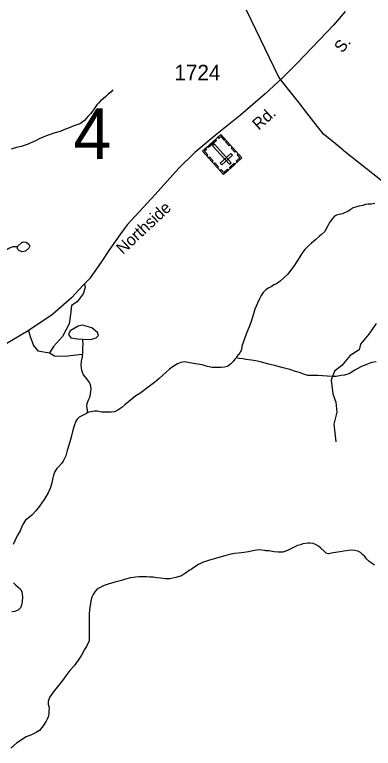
# Model space of a CAD drawing. Extents: x 2056842 to 2160602, y 826753 to 1016856.
# Drawn here: x 2087342 to 2090235, y 854040 to 859964 of the extents above; entities that cross this region are included whole.
import ezdxf

# ---------------------------------------------------------------- set-up
doc = ezdxf.new("R2010")
doc.units = 0
for name, color, linetype in [('Exist Boundary Political City Limit New', 7, 'Continuous'), ('Exist Cultural Cemetery CELL', 7, 'Continuous'), ('Exist Hydrographic Creek Single Shore', 7, 'Continuous'), ('Exist Hydrographic Misc Water Feature', 7, 'Continuous'), ('Exist Road Non-System Type 51', 7, 'Continuous'), ('Exist Road Secondary Structure Standard Bridge Number Label', 7, 'Continuous'), ('Exist Road Secondary Type 51 Attributed', 7, 'Continuous'), ('Exist Road Secondary Type 51 Label', 7, 'Continuous'), ('Exist Road Secondary Type 51 Number Label', 7, 'Continuous'), ('Map Preparation Boundary City Limit Buffer Line', 7, 'Continuous')]:
    doc.layers.add(name, color=color, linetype=linetype)

msp = doc.modelspace()

# ---------------------------------------------------------------- linework, layer by layer
at = {"layer": 'Exist Boundary Political City Limit New'}
msp.add_lwpolyline([(2091735, 858766.5), (2090411.6, 858536.4), (2090000, 858863), (2089992.9, 858868.9), (2089910.4, 858937), (2089833.6, 859000.2), (2089688.6, 859184.9), (2089636.1, 859251.8), (2089509.2, 859414.6), (2089471.8, 859460.8), (2089211, 860000)], dxfattribs=at)
at = {"layer": 'Exist Cultural Cemetery CELL'}
for points in [[(2089175.2, 858807), (2089027.4, 858673.7), (2088856.9, 858862.9), (2089004.8, 858996.2)], [(2088969.8, 858949.2), (2088906.7, 858892.3), (2088899.1, 858900.8), (2088962.1, 858957.6)], [(2088980.2, 858974), (2088987.9, 858965.4), (2089004.3, 858980.2), (2089031.3, 858950.2), (2089039.6, 858957.6), (2089004.8, 858996.2)], [(2089051.6, 858944.2), (2089080.6, 858912.1), (2089072.2, 858904.4), (2089043.2, 858936.6)], [(2088881.5, 858885), (2088889.2, 858876.5), (2088872.8, 858861.8), (2088899.9, 858831.8), (2088891.6, 858824.3), (2088856.9, 858862.9)], [(2089074.6, 858755.8), (2089088.5, 858768.3), (2088952.7, 858918.9), (2088938.9, 858906.4)], [(2089096.6, 858894.3), (2089125.6, 858862.1), (2089117.2, 858854.5), (2089088.2, 858886.7)], [(2089099.4, 858830.3), (2089086.9, 858844.1), (2088999.4, 858765.3), (2089011.9, 858751.4)], [(2089146.2, 858839.2), (2089137.8, 858831.6), (2089159.4, 858807.7), (2089129.2, 858780.5), (2089136.7, 858772.3), (2089175.2, 858807)], [(2088913.7, 858816.8), (2088942.7, 858784.6), (2088934.3, 858777), (2088905.3, 858809.2)], [(2088957.8, 858767.8), (2088986.8, 858735.6), (2088978.4, 858728), (2088949.4, 858760.2)], [(2089120.2, 858757.4), (2089081.7, 858722.7), (2089074.1, 858731.2), (2089112.6, 858765.9)], [(2088998.3, 858705.9), (2089006.7, 858713.5), (2089028.3, 858689.6), (2089058.4, 858716.7), (2089065.8, 858708.5), (2089027.3, 858673.7)]]:
    msp.add_lwpolyline(points, close=True, dxfattribs=at)
at = {"layer": 'Exist Hydrographic Creek Single Shore'}
for points in [[(2088132.7, 859357.5), (2088116.5, 859337.2), (2088096.8, 859321.2), (2088076.9, 859303.1), (2088055.2, 859285.3), (2088033.1, 859267.2), (2088021, 859251.1), (2088005.2, 859234.9), (2087989.2, 859212.9), (2087977.1, 859196.9), (2087955.1, 859166.9), (2087933.2, 859142.7), (2087917.6, 859124.8), (2087905.5, 859110.8), (2087873.3, 859086.5), (2087851.8, 859076.3), (2087819.4, 859066.2), (2087781.5, 859050.5), (2087737.6, 859034), (2087708.1, 859020.2), (2087658, 859007.9), (2087619.9, 858993.8), (2087576, 858977.7), (2087539.9, 858961.7), (2087516.1, 858949.5), (2087486.2, 858935.3), (2087441.9, 858915.3), (2087394.1, 858901), (2087356.4, 858890.9), (2087312.3, 858879)], [(2090247.4, 858440.1), (2090235.1, 858435.9), (2090217.5, 858433.7), (2090194.9, 858433.9), (2090173.4, 858431.9), (2090149.4, 858423.7), (2090121.3, 858417.8), (2090091.4, 858409.4), (2090073.5, 858403.6), (2090049.3, 858389.4), (2090029.7, 858375.3), (2090009.4, 858365.5), (2089985.4, 858357.3), (2089959.3, 858351.1), (2089937.6, 858345.1), (2089921.8, 858336.9), (2089905.6, 858319.1), (2089881.6, 858287), (2089872, 858265), (2089851.7, 858230.7), (2089842, 858210.6), (2089818, 858188.7), (2089802, 858174.5), (2089772.1, 858148.6), (2089736.2, 858118.4), (2089712, 858096.4), (2089682.3, 858068.5), (2089658.3, 858036.4), (2089642.5, 858008.4), (2089618.7, 857972.2), (2089592.9, 857934), (2089566.9, 857898.1), (2089545.3, 857867.7), (2089512.9, 857839.7), (2089483.2, 857811.8), (2089453, 857791.6), (2089431.5, 857781.5), (2089411.2, 857767.5), (2089387.6, 857755.3), (2089367.3, 857743.4), (2089347.4, 857721.2), (2089331.7, 857697.2), (2089315.9, 857669.2), (2089299.9, 857635.1), (2089278.1, 857585.2), (2089264, 857528.9), (2089246.6, 857477.2), (2089234.5, 857442.9), (2089212.5, 857391), (2089196.7, 857346.8), (2089174.8, 857286.8), (2089175, 857282.7), (2089171.1, 857256.9), (2089157.2, 857234.7), (2089146.9, 857218.9), (2089135.2, 857202.8), (2089128.6, 857192.4)], [(2089128.6, 857192.4), (2089119.2, 857182.9), (2089103.2, 857162.6), (2089085.2, 857144.6), (2089073.5, 857134.6), (2089057.7, 857124.4), (2089035.4, 857118.5), (2089007.5, 857116.2), (2088975.7, 857114.1), (2088935.7, 857116.2), (2088897.6, 857121.9), (2088853.5, 857135.9), (2088799.5, 857143.7), (2088753.6, 857153.5), (2088711.2, 857159.5), (2088681.6, 857155.1), (2088655.4, 857145.2), (2088633.5, 857131.1), (2088613.6, 857119.1), (2088591.4, 857100.9), (2088567.8, 857079), (2088535.4, 857051), (2088507.8, 857026.8), (2088470.2, 856992.8), (2088420, 856956.5), (2088384.1, 856930.3), (2088352.1, 856906.4), (2088320.3, 856886.5), (2088276.5, 856850.1), (2088230.5, 856814), (2088206.3, 856792.1), (2088174.5, 856769.7), (2088146.7, 856757.7), (2088120.6, 856753.6), (2088094.6, 856753.5), (2088074.7, 856753.6), (2088044.7, 856755.3), (2088006.6, 856761.1), (2087984.5, 856761.2), (2087958.8, 856757), (2087940.8, 856753.3), (2087930.7, 856749.1)], [(2090257.3, 857162.1), (2090223.2, 857154.3), (2090192.9, 857143.9), (2090133.4, 857120), (2090087.3, 857093.7), (2090049.3, 857069.5), (2090037.2, 857063.6), (2090001.6, 857053.6), (2089975.3, 857049.4), (2089935.3, 857041.3), (2089901.7, 857043.2), (2089787.3, 857050.8), (2089707.5, 857050.7), (2089673.3, 857060.3), (2089647.8, 857072.3), (2089607.7, 857084.1), (2089561.5, 857100), (2089507.4, 857111.9), (2089447.5, 857127.8), (2089391.1, 857141.6), (2089333.5, 857157.3), (2089301.1, 857165.4), (2089251.5, 857173), (2089207.4, 857180.9), (2089185.5, 857185), (2089153.1, 857186.7), (2089128.6, 857192.4)], [(2087930.7, 856749.1), (2087921.1, 856744.9), (2087900.8, 856732.9), (2087862.9, 856714.7), (2087845, 856696.8), (2087835, 856682.8), (2087821, 856644.8), (2087811.2, 856608.6), (2087797.7, 856552.6), (2087781.5, 856496.6), (2087765.7, 856444.7), (2087755.6, 856402.7), (2087733.9, 856358.6), (2087720.2, 856340.4), (2087698.4, 856316.5), (2087682, 856300.3), (2087666.2, 856274.3), (2087654.3, 856246.1), (2087650.4, 856224.3), (2087640.6, 856184.1), (2087631, 856146.1), (2087612.9, 856104.2), (2087580.9, 856049.8), (2087543, 855996), (2087511.6, 855957.7), (2087485.4, 855927.6), (2087479.2, 855921.6), (2087465.3, 855909.5), (2087439.4, 855891.5), (2087429.6, 855881.7), (2087411.5, 855851.6), (2087397.4, 855823.7), (2087385.9, 855797.4), (2087365.8, 855761.5), (2087346.1, 855721.5), (2087330.1, 855685.4)], [(2090246, 855518.5), (2090228.1, 855528.5), (2090198.2, 855552.1), (2090180, 855570.3), (2090165.8, 855588.2), (2090148, 855606), (2090132.2, 855620.2), (2090109.8, 855632.1), (2090085.8, 855637.7), (2090053.8, 855639.7), (2090020, 855635.5), (2089998.1, 855631.5), (2089968.1, 855625.5), (2089912, 855617.4), (2089874, 855611.4), (2089853.7, 855615.2), (2089839.8, 855633.2), (2089811.9, 855656.9), (2089793.8, 855671), (2089769.9, 855684.8), (2089749.8, 855692.7), (2089723.7, 855696.6), (2089705.9, 855696.5), (2089667.9, 855690.5), (2089647.8, 855682.6), (2089623.9, 855676.5), (2089591.9, 855660.2), (2089544.1, 855638.3), (2089504.3, 855624), (2089468, 855623.8), (2089434, 855627.8), (2089391.9, 855633.7), (2089368.2, 855635.7), (2089360.4, 855637.7), (2089312.2, 855641.4), (2089264, 855635.3), (2089228.1, 855627.3), (2089172.1, 855617.1), (2089116.1, 855612.7), (2089076.2, 855604.9), (2089036.2, 855594.7), (2089008.5, 855586.4), (2088904.5, 855556.3), (2088898.6, 855554.3), (2088862.1, 855542), (2088824.4, 855524.2), (2088788.5, 855500), (2088764.5, 855483.8), (2088748.7, 855475.6), (2088718.8, 855453.8), (2088688.6, 855433.6), (2088642.9, 855419.4), (2088618.9, 855413.3), (2088594.9, 855409.3), (2088558.6, 855409.1), (2088519, 855413.1), (2088484.8, 855417), (2088458.5, 855421), (2088430.9, 855422.7), (2088404.8, 855424.6), (2088370.8, 855424.5), (2088342.7, 855424.3)], [(2088342.7, 855424.3), (2088319.1, 855422.2), (2088276.9, 855416.5), (2088235.2, 855406.1), (2088202.8, 855396), (2088151, 855382), (2088097.2, 855365.8), (2088065, 855353.6), (2088053.4, 855349.7), (2088031.2, 855339.3), (2088015, 855329.6), (2088003.1, 855319.6), (2087989, 855303.5), (2087975.2, 855281.3), (2087963.5, 855259.5), (2087957.4, 855231.2), (2087953.5, 855207.4), (2087949.4, 855183.3), (2087944.1, 855125.3), (2087943.9, 855057.6), (2087942.2, 855001.4), (2087944.1, 854949.2), (2087942.6, 854907.2), (2087920.3, 854863.1), (2087904.5, 854837.1), (2087880.7, 854791.2), (2087852.8, 854751.2), (2087820.8, 854707), (2087787.4, 854667), (2087755.4, 854624.8), (2087727.7, 854586.8), (2087683.4, 854532.6), (2087653.7, 854494.5), (2087623.8, 854450.3), (2087612.1, 854418.5), (2087611.9, 854396.6), (2087618.4, 854376.5), (2087620.1, 854364.5), (2087618.2, 854342.5), (2087616.4, 854316.3), (2087612.3, 854294.2), (2087604.3, 854274.4), (2087596.5, 854260.2), (2087570.7, 854222.3), (2087560.6, 854208.4), (2087540.9, 854184.2), (2087514.9, 854166.2), (2087478.6, 854149.8), (2087434.7, 854133.7), (2087357.5, 854081.9), (2087310.1, 854039.7)], [(2087333, 855375.3), (2087351.3, 855357.5), (2087371.2, 855341.5), (2087383, 855331.7), (2087391.2, 855321.5), (2087399.2, 855303.6), (2087403.6, 855283.5), (2087403.8, 855261.6), (2087401.5, 855225.4), (2087399.7, 855209.4), (2087395.8, 855195.4), (2087387.8, 855173.5), (2087379.6, 855165.4), (2087372, 855157.6), (2087355.8, 855149.5), (2087342, 855143.5), (2087319.9, 855141.2)]]:
    msp.add_lwpolyline(points, dxfattribs=at)
at = {"layer": 'Exist Hydrographic Misc Water Feature'}
for points in [[(2087364.9, 858091.9), (2087399.1, 858124.9), (2087416.3, 858130.2), (2087433.4, 858127.5), (2087457.1, 858111.7), (2087465, 858094.6), (2087455.8, 858077.4), (2087428.1, 858055), (2087399.1, 858049.7), (2087379.4, 858059), (2087363.6, 858073.5), (2087364.9, 858091.9)], [(2087212, 858016.8), (2087255.5, 858055), (2087295, 858078.7), (2087330.6, 858091.9), (2087354.3, 858091.9), (2087364.9, 858091.9)], [(2087891, 857342.7), (2087955.6, 857340.1), (2088000.4, 857353.3), (2088018.9, 857374.4), (2088011, 857398.1), (2087963.5, 857435), (2087889.8, 857456.1), (2087852.9, 857448.2), (2087789.6, 857411.3), (2087776.4, 857382.3), (2087794.9, 857355.9), (2087847.6, 857345.4), (2087891, 857342.7)], [(2087930.7, 856749.1), (2087930.7, 856762.9), (2087928.7, 856773), (2087924.4, 856801.2), (2087926.8, 856823.2), (2087928.5, 856833), (2087940.6, 856859.2), (2087948.2, 856875.1), (2087950.2, 856884.9), (2087954.1, 856903), (2087958, 856939.3), (2087956, 856965.2), (2087950, 856983.1), (2087939.8, 857002.9), (2087913.9, 857036.9), (2087897.7, 857056.8), (2087884, 857090.9), (2087877.6, 857132.9), (2087881.7, 857166.8), (2087889.5, 857200.9), (2087893, 857242.9), (2087893, 857270.9), (2087893.2, 857307), (2087890.8, 857328.9), (2087891, 857342.7)]]:
    msp.add_lwpolyline(points, dxfattribs=at)
at = {"layer": 'Exist Road Non-System Type 51'}
for points in [[(2087904.8, 857790.3), (2087911.4, 857760.5), (2087894.8, 857710.6), (2087844.9, 857644.1), (2087799.2, 857615), (2087793, 857544.4), (2087780.5, 857467.5), (2087726.5, 857365.6), (2087653.8, 857284.6), (2087621.6, 857233.6)], [(2090258.4, 857469.5), (2090198.2, 857384.3), (2090131.7, 857303.3), (2090122.4, 857258.6), (2090049.7, 857210.8), (2089981.1, 857131.8), (2089920.9, 857086.1), (2089896, 857013.3), (2089908.4, 856901.1), (2089933.4, 856834.6), (2089939.6, 856753.5), (2089917.8, 856656.9), (2089932.3, 856515.5)], [(2087453.7, 857412.6), (2087468, 857366.7), (2087492.9, 857291.8), (2087528.2, 857250.3), (2087621.6, 857233.6)], [(2087621.6, 857233.6), (2087663.2, 857208.7), (2087746.3, 857206.6), (2087885.4, 857223.2)]]:
    msp.add_lwpolyline(points, dxfattribs=at)
at = {"layer": 'Exist Road Secondary Type 51 Attributed'}
for points in [[(2090008.4, 859991.2), (2089913.9, 859880), (2089621.6, 859574), (2089499.1, 859450.3), (2089363.6, 859325.1), (2089163.1, 859153.7), (2088976.2, 859003), (2088795, 858850.7), (2088666.2, 858726), (2088474.1, 858513), (2088250.3, 858266.2), (2088189.1, 858187.2), (2088101.8, 858060.4), (2088043.7, 857974.2), (2087944.5, 857832.3), (2087895.1, 857780.1)], [(2087895.1, 857780.1), (2087799.1, 857678.5), (2087646.5, 857543.4), (2087449.7, 857409.9), (2087040.5, 857169.9)]]:
    msp.add_lwpolyline(points, dxfattribs=at)
at = {"layer": 'Map Preparation Boundary City Limit Buffer Line'}
msp.add_lwpolyline([(2091735, 858766.5), (2090411.6, 858536.4), (2090000, 858863), (2089992.9, 858868.9), (2089910.4, 858937), (2089833.6, 859000.2), (2089688.6, 859184.9), (2089636.1, 859251.8), (2089509.2, 859414.6), (2089471.8, 859460.8), (2089211, 860000)], dxfattribs=at)

# ---------------------------------------------------------------- texts
at = {"layer": 'Exist Road Secondary Structure Standard Bridge Number Label'}
msp.add_text('4', height=410.1, dxfattribs=at).set_placement((2087816.6, 858797.7))
at = {"layer": 'Exist Road Secondary Type 51 Label'}
for s, rotation, p in [('S.', 50.79792, (2089984.2, 859649.2)), ('Rd.', 42.02513, (2089311.4, 859026.5)), ('Northside', 43.02757, (2088214.9, 858023.5))]:
    msp.add_text(s, height=95, rotation=rotation, dxfattribs=at).set_placement(p)
at = {"layer": 'Exist Road Secondary Type 51 Number Label'}
msp.add_text('1724', height=125, dxfattribs=at).set_placement((2088630, 859434.6))

doc.saveas('drawing.dxf')
